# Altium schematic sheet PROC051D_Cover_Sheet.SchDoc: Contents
size 431 x 279 mm; Date: Not shown in title block; ApprovedBy: Not shown in title block; CheckedBy: Not shown in title block; Author: Not shown in title block; CompanyName: Not shown in title block; Engineer: Not shown in title block; Organization: Not shown in title block; Address1: Not shown in title block; Address2: Not shown in title block; Address3: Not shown in title block; Address4: Not shown in title block; DocumentNumber: 1; Revision: Use project parameter SCH_Rev; SheetNumber: 1; SheetTotal: 16; PageSetup: Record=PageOptions¦CenterHorizontal=True¦CenterVertical=True¦PrintScale=0.64¦XCorrection=1.00¦YCorrection=1.00¦PrintKind=0¦BorderSize=5000000¦LeftOffset=0¦BottomOffset=0¦Orientation=2¦PaperLength=1000¦PaperWidth=1000¦Scale=100¦PaperSource=15¦PrintQuality=600¦MediaType=1¦DitherType=10¦PrintScaleMode=1¦PaperKind=Letter
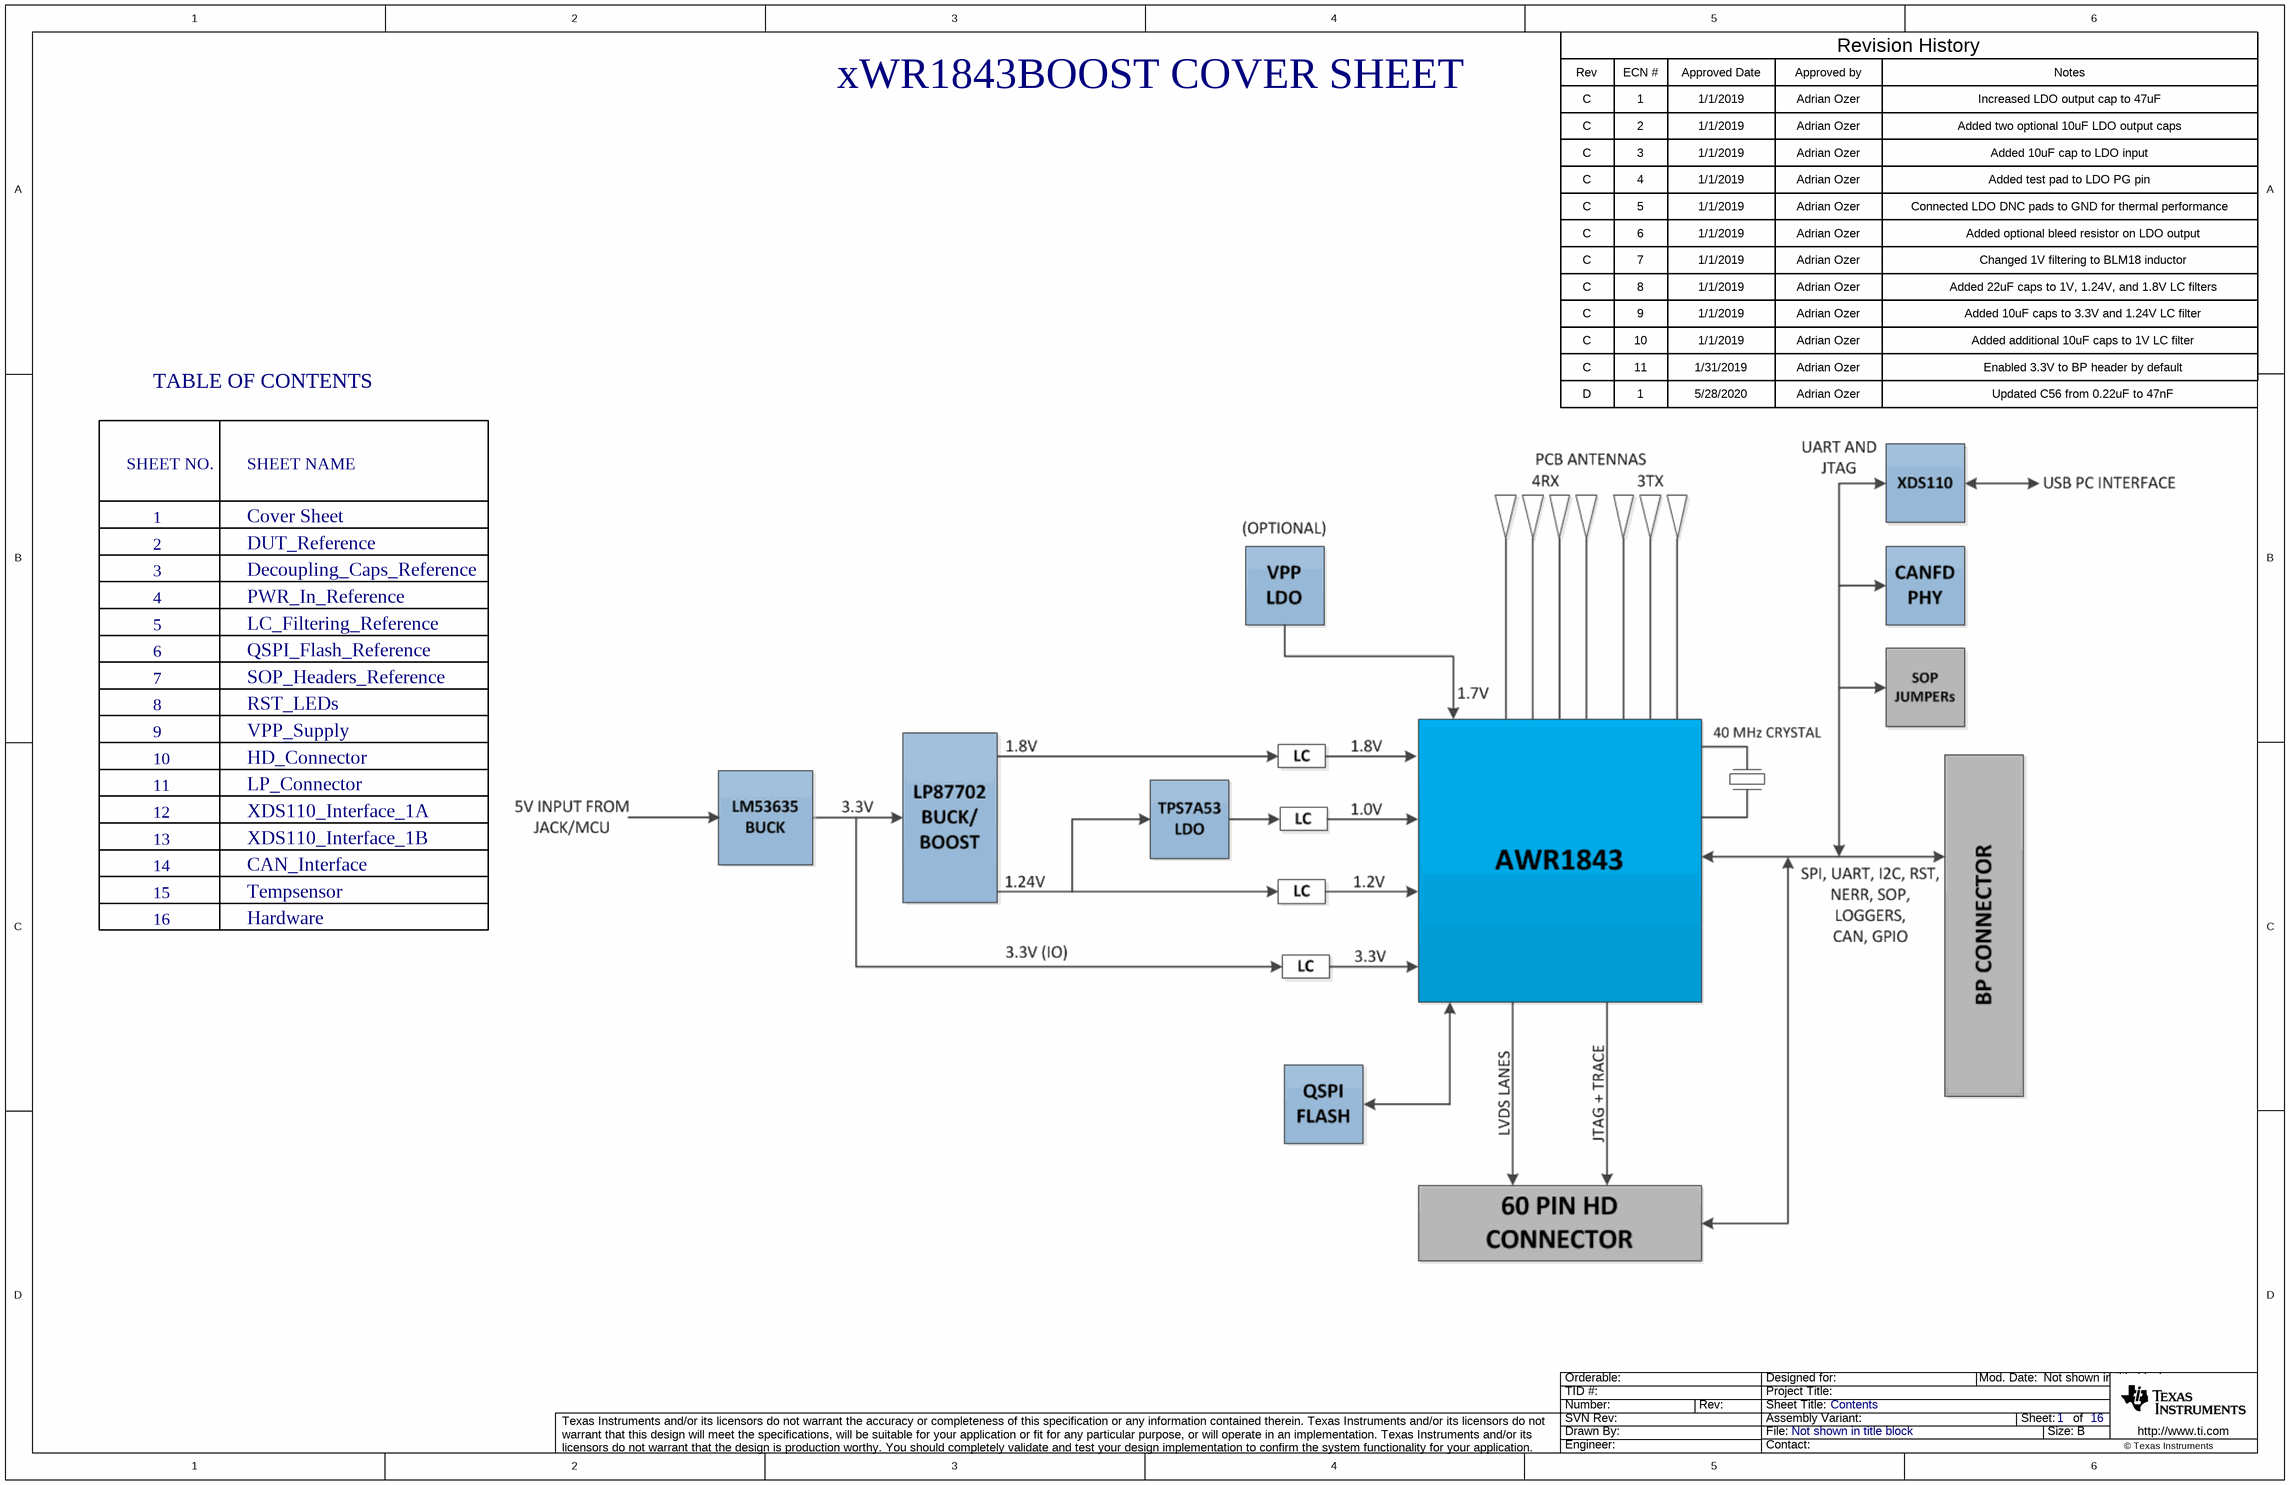
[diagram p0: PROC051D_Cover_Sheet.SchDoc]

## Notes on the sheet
- xWR1843BOOST COVER SHEET
- Rev
- C
- ECN #
- 1
- Approved Date
- 1/1/2019
- Approved by
- Adrian Ozer
- Revision History
- Notes
- Increased LDO output cap to 47uF
- 2
- 3
- Added two optional 10uF LDO output caps
- Added 10uF cap to LDO input
- 4
- 5
- 6
- Added test pad to LDO PG pin
- Connected LDO DNC pads to GND for thermal performance
- Added optional bleed resistor on LDO output
- 7
- 8
- Changed 1V filtering to BLM18 inductor
- Added 22uF caps to 1V, 1.24V, and 1.8V LC filters
- 9
- 10
- 11
- 1/31/2019
- Added 10uF caps to 3.3V and 1.24V LC filter
- Added additional 10uF caps to 1V LC filter
- Enabled 3.3V to BP header by default
- TABLE OF CONTENTS
- D
- 5/28/2020
- Updated C56 from 0.22uF to 47nF
- SHEET NO.
- SHEET NAME
- Cover Sheet
- DUT_Reference
- Decoupling_Caps_Reference
- PWR_In_Reference
- LC_Filtering_Reference
- QSPI_Flash_Reference
- SOP_Headers_Reference
- RST_LEDs
- VPP_Supply
- HD_Connector
- 12
- LP_Connector
- XDS110_Interface_1A
- 13
- 15
- 14
- XDS110_Interface_1B
- Tempsensor
- CAN_Interface
- 16
- Hardware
